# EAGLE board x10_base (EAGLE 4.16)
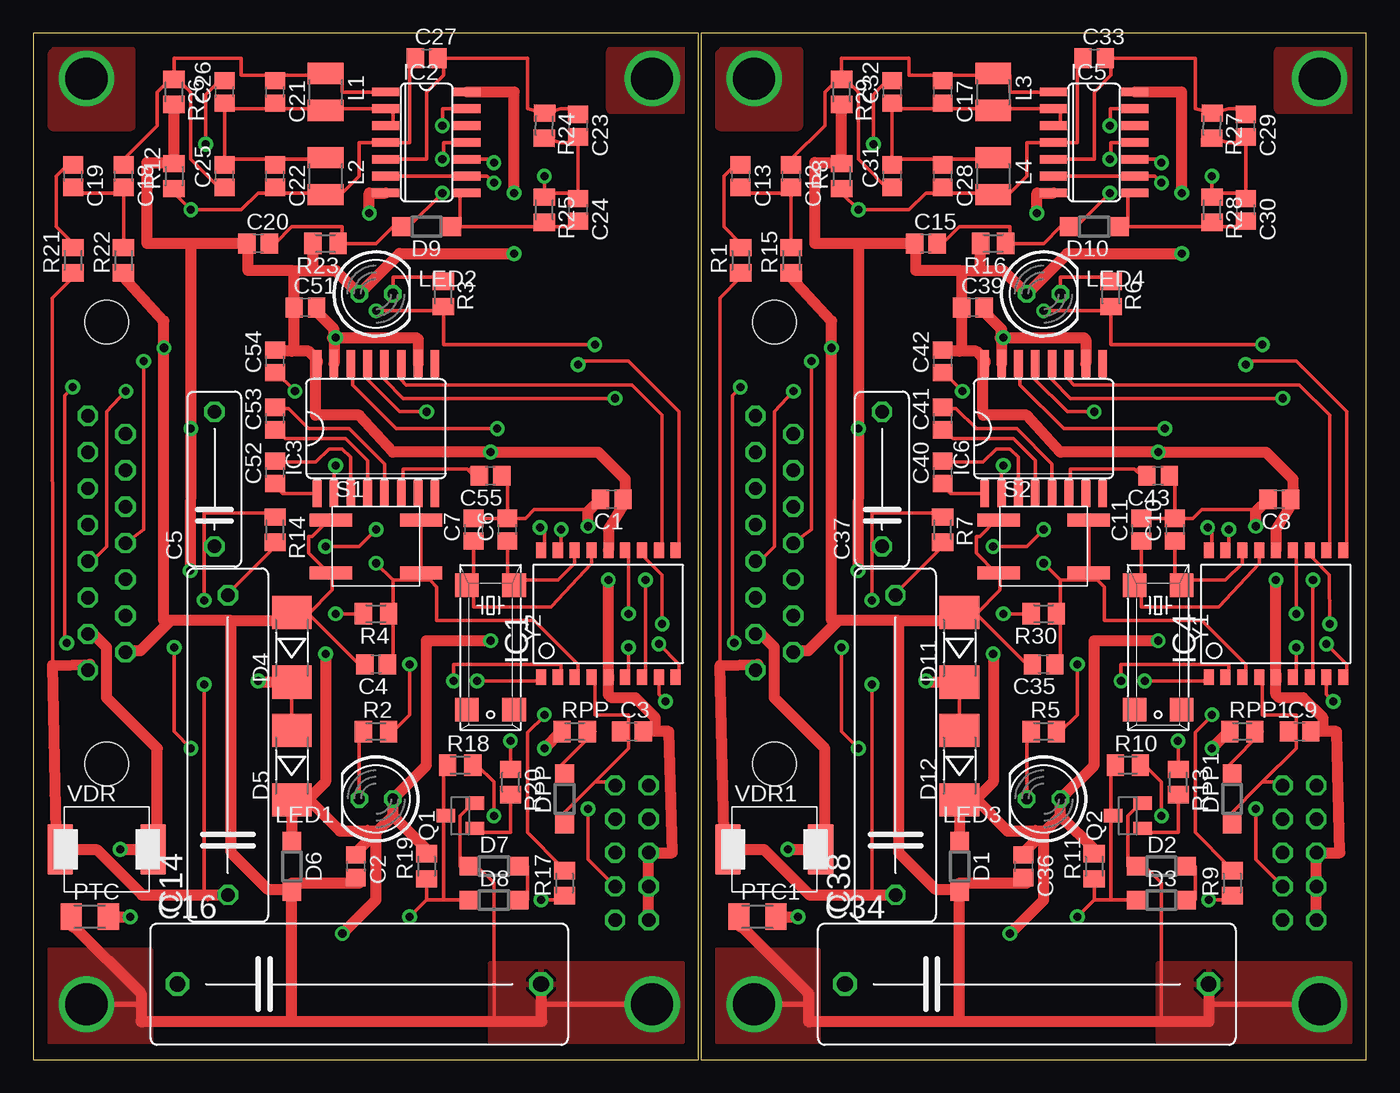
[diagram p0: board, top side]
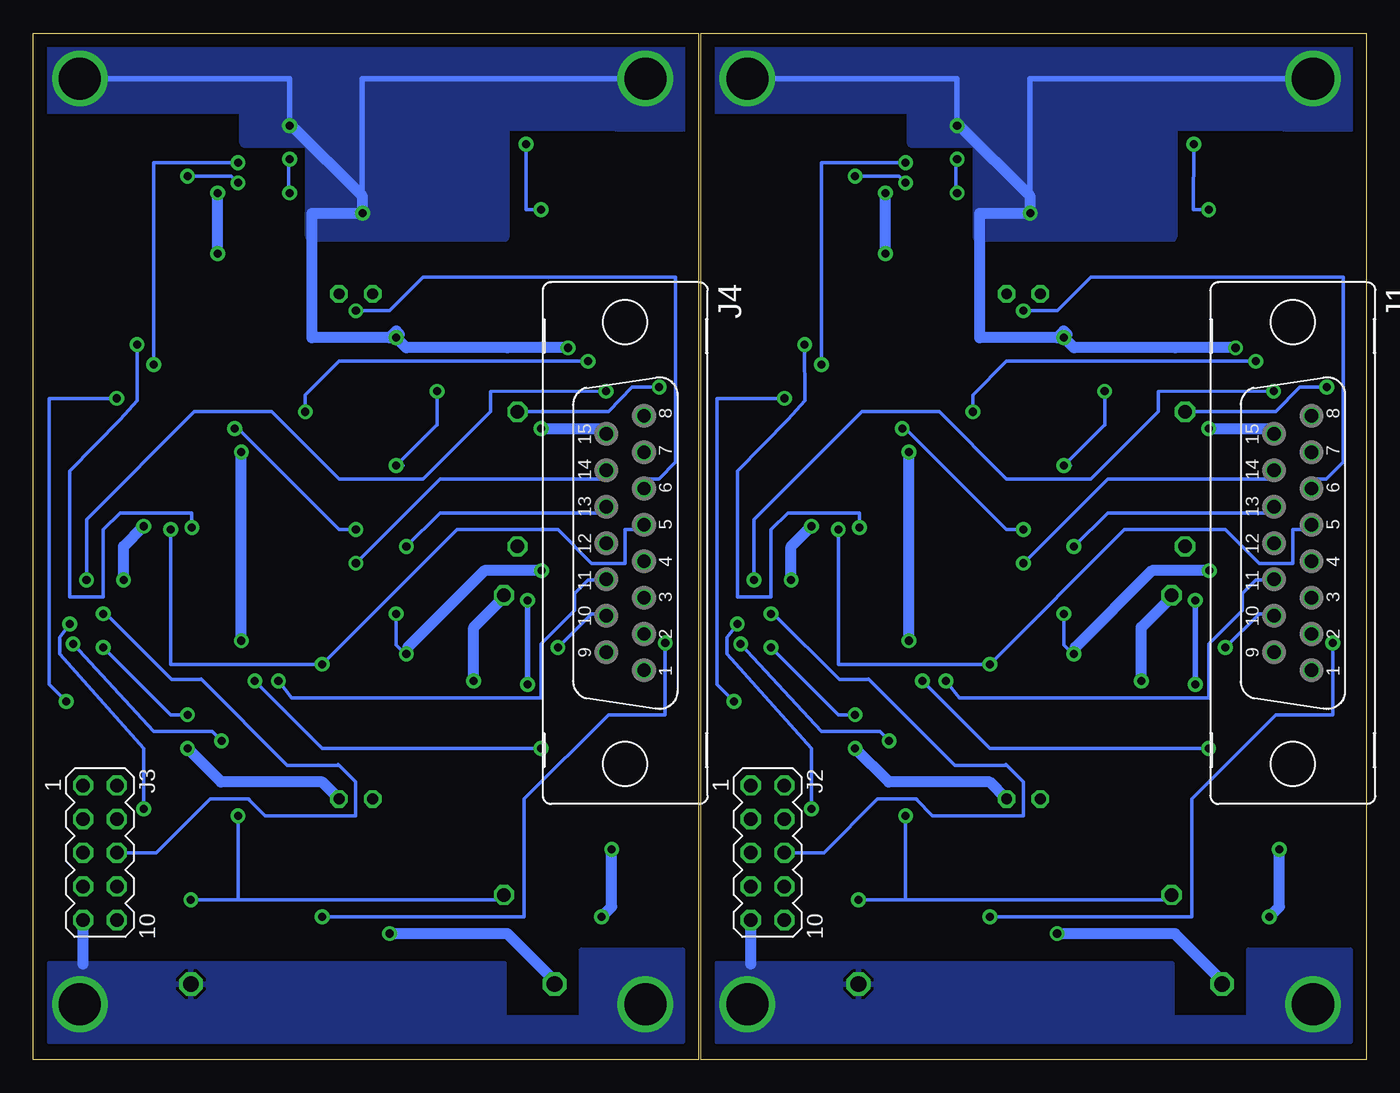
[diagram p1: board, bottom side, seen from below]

Size 100.58 x 77.46 mm. Coordinates in mm from the lower left corner, seen from the top.
Outline: 0,0 50.22,0 50.22,77.46 0,77.46 0,0
Outline: 50.37,0 100.58,0 100.58,77.46 50.37,77.46 50.37,0
Copper layers (1*16): Top 0.035mm / dielectric 1.5mm / Bottom 0.035mm
Design rules "default": minimum track width 10mil, minimum drill 24mil, track to track 10mil, track to pad 10mil, pad to pad 10mil, via to via 10mil, smd to smd 10mil, copper to edge 40mil, drill to drill 8mil, minimum pad ring 10mil, minimum via ring 10mil, stop-mask expansion 4mil, vias tented up to drill 0mil, thermal gap 10mil

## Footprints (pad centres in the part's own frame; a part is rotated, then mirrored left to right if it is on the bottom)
C0805 = smd 1.3 x 1.5: 1 -0.85,0; 2 0.85,0
C102-043X133 = drill 1.016 octagon: 1 -5.08,0; 2 5.08,0
C225-062X268 = drill 1.016 octagon: 1 -11.303,0; 2 11.303,0
C275-093X316 = drill 1.194 octagon: 1 -13.716,0; 2 13.716,0
SOD123 = smd 1.4 x 1.4: A 1.9,0; C -1.9,0
MELF-MLL41 = smd 2.5 x 3: A 2.625,0; C -2.625,0
SO-18W = smd 0.762 x 1.143: 1 -5.08,-4.788; 2 -3.81,-4.788; 3 -2.54,-4.788; 4 -1.27,-4.788; 5 0,-4.788; 6 1.27,-4.788; 7 2.54,-4.788; 8 3.81,-4.788; 9 5.08,-4.788; 10 5.08,4.788; 11 3.81,4.788; 12 2.54,4.788; 13 1.27,4.788; 14 0,4.788; 15 -1.27,4.788; 16 -2.54,4.788; 17 -3.81,4.788; 18 -5.08,4.788
SO14 = smd 0.66 x 2.032: 1 -3.81,-3.073; 2 -2.54,-3.073; 3 -1.27,-3.073; 4 0,-3.073; 5 1.27,-3.073; 6 2.54,-3.073; 7 3.81,-3.073; 8 3.81,3.073; 9 2.54,3.073; 10 1.27,3.073; 11 0,3.073; 12 -1.27,3.073; 13 -2.54,3.073; 14 -3.81,3.073
SO16L = smd 0.66 x 2.032: 1 -4.445,-4.902; 2 -3.175,-4.902; 3 -1.905,-4.902; 4 -0.635,-4.902; 5 0.635,-4.902; 6 1.905,-4.902; 7 3.175,-4.902; 8 4.445,-4.902; 9 4.445,4.902; 10 3.175,4.902; 11 1.905,4.902; 12 0.635,4.902; 13 -0.635,4.902; 14 -1.905,4.902; 15 -3.175,4.902; 16 -4.445,4.902
F15V = drill 1.016 octagon: 1 9.601,1.422; 2 6.858,1.422; 3 4.115,1.422; 4 1.372,1.422; 5 -1.372,1.422; 6 -4.115,1.422; 7 -6.858,1.422; 8 -9.601,1.422; 9 8.23,-1.422; 10 5.486,-1.422; 11 2.743,-1.422; 12 0,-1.422; 13 -2.743,-1.422; 14 -5.486,-1.422; 15 -8.23,-1.422 | hole 3.302: 16.662,0; -16.662,0
MA05-2 = drill 1.016 octagon: 1 -5.08,-1.27; 2 -5.08,1.27; 3 -2.54,-1.27; 4 -2.54,1.27; 5 0,-1.27; 6 0,1.27; 7 2.54,-1.27; 8 2.54,1.27; 9 5.08,-1.27; 10 5.08,1.27
L1210 = smd 1.6 x 2.7: 1 -1.4,0; 2 1.4,0
LED5MM = drill 0.813 octagon: A -1.27,0; K 1.27,0
M1206 = smd 1.6 x 2: 1 -1.4,0; 2 1.4,0
SOT23 = smd 1 x 1.4: 1 -0.95,-1.1; 2 0.95,-1.1; 3 0,1.1
M0805 = smd 1.3 x 1.6: 1 -0.95,0; 2 0.95,0
EVQQ2 = smd 3.2 x 1: A -3.4,-2; AP -3.4,2; B 3.4,-2; BP 3.4,2
VDR130V = smd 1.93 x 3.81: P$1 -3.5,0; P$2 3.5,0
MM39SL = smd 1.778 x 1.778: 1 -4.699,-1.778; 2 4.699,-1.778; 3 4.699,1.778; 4 -4.699,1.778

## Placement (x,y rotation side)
C1  0.1uF  [C0805]  43.65,42.29 180 top
C2  0.1uF  [C0805]  24.35,14.6 270 top
C3  0.1uF  [C0805]  45.17,24.76 0 top
C4  0.1uF  [C0805]  25.87,29.84 180 top
C5  0.1uF  [C102-043X133]  13.68,43.81 90 top
C6  15pF  [C0805]  35.78,40 90 top
C7  15pF  [C0805]  33.24,40 90 top
C8  0.1uF  [C0805]  94.02,42.29 180 top
C9  0.1uF  [C0805]  95.54,24.76 0 top
C10  15pF  [C0805]  86.14,40 90 top
C11  15pF  [C0805]  83.6,40 90 top
C12  150pF  [C0805]  57.19,66.67 270 top
C13  150pF  [C0805]  53.38,66.67 270 top
C14  1.0uF  [C225-062X268]  14.69,23.74 90 top
C15  0.01uF  [C0805]  67.35,61.59 0 top
C16  470uF  [C275-093X316]  24.6,5.71 0 top
C17  3300pF  [C0805]  68.62,73.02 270 top
C18  150pF  [C0805]  6.82,66.67 270 top
C19  150pF  [C0805]  3.01,66.67 270 top
C20  0.01uF  [C0805]  16.98,61.59 0 top
C21  3300pF  [C0805]  18.25,73.02 270 top
C22  3300pF  [C0805]  18.25,66.67 270 top
C23  10pF  [C0805]  41.11,70.48 270 top
C24  10pF  [C0805]  41.11,64.13 270 top
C25  4700pF  [C0805]  14.44,66.67 90 top
C26  4700pF  [C0805]  14.44,73.02 90 top
C27  100pF  [C0805]  29.68,75.56 0 top
C28  3300pF  [C0805]  68.62,66.67 270 top
C29  10pF  [C0805]  91.48,70.48 270 top
C30  10pF  [C0805]  91.48,64.13 270 top
C31  4700pF  [C0805]  64.81,66.67 90 top
C32  4700pF  [C0805]  64.81,73.02 90 top
C33  100pF  [C0805]  80.05,75.56 0 top
C34  470uF  [C275-093X316]  74.97,5.71 0 top
C35  0.1uF  [C0805]  76.24,29.84 180 top
C36  0.1uF  [C0805]  74.71,14.6 270 top
C37  0.1uF  [C102-043X133]  64.05,43.81 90 top
C38  1.0uF  [C225-062X268]  65.06,23.74 90 top
C39  0.1uF  [C0805]  70.9,56.76 0 top
C40  0.1uF  [C0805]  68.62,44.32 90 top
C41  0.1uF  [C0805]  68.62,48.38 90 top
C42  0.1uF  [C0805]  68.62,52.7 90 top
C43  0.1uF  [C0805]  84.87,44.06 180 top
C51  0.1uF  [C0805]  20.54,56.76 0 top
C52  0.1uF  [C0805]  18.25,44.32 90 top
C53  0.1uF  [C0805]  18.25,48.38 90 top
C54  0.1uF  [C0805]  18.25,52.7 90 top
C55  0.1uF  [C0805]  34.51,44.06 180 top
D1  5.1V  [SOD123]  69.89,14.6 270 top
D2  6.8V  [SOD123]  85.13,14.6 0 top
D3  6.8V  [SOD123]  85.13,12.06 0 top
D4  DL4005  [MELF-MLL41]  19.52,31.11 90 top
D5  DL4005  [MELF-MLL41]  19.52,22.22 90 top
D6  5.1V  [SOD123]  19.52,14.6 270 top
D7  6.8V  [SOD123]  34.76,14.6 0 top
D8  6.8V  [SOD123]  34.76,12.06 0 top
D9  1N4148S  [SOD123]  29.68,62.86 180 top
D10  1N4148S  [SOD123]  80.05,62.86 180 top
D11  DL4005  [MELF-MLL41]  69.89,31.11 90 top
D12  DL4005  [MELF-MLL41]  69.89,22.22 90 top
DPP  1N4148S  [SOD123]  40.09,19.68 90 top
DPP1  1N4148S  [SOD123]  90.46,19.68 90 top
IC1  PIC16F87ASO  [SO-18W]  43.4,33.65 0 top
IC2  4069D  [SO14]  29.68,69.21 270 top
IC3  MAX232ECWE  [SO16L]  25.87,47.62 0 top
IC4  PIC16F87ASO  [SO-18W]  93.76,33.65 0 top
IC5  4069D  [SO14]  80.05,69.21 270 top
IC6  MAX232ECWE  [SO16L]  76.24,47.62 0 top
J1  [F15V]  5.55,38.98 270 bottom
J2  [MA05-2]  45.17,15.62 270 bottom
J3  [MA05-2]  95.54,15.62 270 bottom
J4  [F15V]  55.92,38.98 270 bottom
L1  220uH  [L1210]  22.06,73.02 270 top
L2  220uH  [L1210]  22.06,66.67 270 top
L3  220uH  [L1210]  72.43,73.02 270 top
L4  220uH  [L1210]  72.43,66.67 270 top
LED1  [LED5MM]  25.87,19.68 180 top
LED2  [LED5MM]  25.87,57.78 0 top
LED3  [LED5MM]  76.24,19.68 180 top
LED4  [LED5MM]  76.24,57.78 0 top
PTC  [M1206]  4.28,10.79 0 top
PTC1  [M1206]  54.65,10.79 0 top
Q1  2N2222S  [SOT23]  32.22,18.41 90 top
Q2  2N2222S  [SOT23]  82.59,18.41 90 top
R1  10K  [M0805]  53.38,60.32 90 top
R2  680  [M0805]  25.87,24.76 0 top
R3  680  [M0805]  30.95,57.78 270 top
R4  10K  [M0805]  25.87,33.65 180 top
R5  680  [M0805]  76.24,24.76 0 top
R6  680  [M0805]  81.32,57.78 270 top
R7  1M  [M0805]  68.62,40 270 top
R8  470K  [M0805]  61,66.67 90 top
R9  5M  [M0805]  90.46,13.33 90 top
R10  1M  [M0805]  82.59,22.22 0 top
R11  50  [M0805]  80.05,14.6 90 top
R12  470K  [M0805]  10.63,66.67 90 top
R13  200  [M0805]  86.4,20.95 270 top
R14  1M  [M0805]  18.25,40 270 top
R15  33K  [M0805]  57.19,60.32 90 top
R16  100K  [M0805]  72.43,61.59 180 top
R17  5M  [M0805]  40.09,13.33 90 top
R18  1M  [M0805]  32.22,22.22 0 top
R19  50  [M0805]  29.68,14.6 90 top
R20  200  [M0805]  36.03,20.95 270 top
R21  10K  [M0805]  3.01,60.32 90 top
R22  33K  [M0805]  6.82,60.32 90 top
R23  100K  [M0805]  22.06,61.59 180 top
R24  220K  [M0805]  38.57,70.48 268.8 top
R25  27K  [M0805]  38.57,64.13 270 top
R26  10M  [M0805]  10.63,73.02 270 top
R27  220K  [M0805]  88.94,70.48 268.8 top
R28  27K  [M0805]  88.94,64.13 270 top
R29  10M  [M0805]  61,73.02 270 top
R30  10K  [M0805]  76.24,33.65 180 top
RPP  10K  [M0805]  40.86,24.76 0 top
RPP1  10K  [M0805]  91.22,24.76 0 top
S1  EVQQ2  [EVQQ2]  25.87,38.73 0 top
S2  EVQQ2  [EVQQ2]  76.24,38.73 0 top
VDR  VARISTORVDR130V  [VDR130V]  5.55,15.87 0 top
VDR1  VARISTORVDR130V  [VDR130V]  55.92,15.87 0 top
Y1  7.68MHz  [MM39SL]  84.87,31.11 270 top
Y2  7.68MHz  [MM39SL]  34.51,31.11 270 top

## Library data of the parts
C1-C43 C51-C55 L1-L4 PTC PTC1 R1-R30 RPP RPP1 = rcl
D1-D12 DPP DPP1 = diode
IC1 IC4 = microchip
IC2 IC5 = 40xx
IC3 IC6 = maxim
J1 J4 = con-subd
J2 J3 = con-lstb
LED1-LED4 = led
Q1 Q2 = transistor-npn
S1 S2 = switch
VDR VDR1 = varistor
Y1 Y2 = crystal

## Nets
+5V: C1.1 C2.1 C16.1 C20.1 C51.1 C54.2 D5.C D6.C IC1.14 IC2.14 IC3.16 J1.15 LED1.A LED2.A R4.2 R12.2 R19.2 R23.2 R26.2 RPP.1
+5V1: C8.1 C15.1 C34.1 C36.1 C39.1 C42.2 D1.C D12.C IC4.14 IC5.14 IC6.16 J4.15 LED3.A LED4.A R8.2 R11.2 R16.2 R29.2 R30.2 RPP1.1
CTL1: IC1.1 J1.10
CTL2: IC1.2 J1.11
CTL3: IC4.2 J4.11
CTL4: IC4.1 J4.10
GND: C1.2 C2.2 C3.2 C4.2 C6.2 C7.2 C16.2 C51.2 C55.1 D4.A D6.A D7.C IC1.5 IC2.7 IC2.13 IC3.10 IC3.15 J1.9 J2.5 J2.7 J2.9 PTC.1 Q1.2 R22.1 S1.A S1.AP
GND1: C8.2 C9.2 C10.2 C11.2 C34.2 C35.2 C36.2 C39.2 C43.1 D1.A D2.C D11.A IC4.5 IC5.7 IC5.13 IC6.10 IC6.15 J3.5 J3.7 J3.9 J4.9 PTC1.1 Q2.2 R15.1 S2.A S2.AP
HOT: C5.1 C14.1 J1.1 R14.1 R17.1 R18.2 R21.1 VDR.P$1
HOT1: C37.1 C38.1 J4.1 R1.1 R7.1 R9.1 R10.2 VDR1.P$1
LED1: IC1.17 J1.5 R2.2
LED2: IC1.18 J1.6 R3.2
LED3: IC4.17 J4.5 R5.2
LED4: IC4.18 J4.6 R6.2
N$1: DPP.A RPP.2
N$2: Q1.1 R20.2
N$3: C6.1 IC1.16 Y2.4
N$4: C7.1 IC1.15 Y2.1
N$5: LED1.K R2.1
N$6: LED2.K R3.1
N$7: IC3.14 J1.13
N$8: C52.1 IC3.1
N$9: C14.2 D4.C D5.A R14.2
N$10: C52.2 IC3.3
N$11: C5.2 D8.C Q1.3 R18.1 R19.1
N$12: D7.A D8.A
N$13: C23.1 C27.2 IC2.5 R24.1
N$14: C23.2 C24.1 IC2.6 IC2.9 R24.2 R25.1
N$15: C18.1 C21.1 C25.1 IC2.1 L1.1 R26.1
N$16: C19.1 R21.2
N$17: C18.2 C19.2 R22.2
N$18: C21.2 C22.1 C25.2 C26.1 IC2.2 IC2.3 L1.2 L2.1
N$19: C22.2 C26.2 C27.1 IC2.4 L2.2 R12.1
N$20: C24.2 D9.C IC2.8 R25.2
N$21: C20.2 D9.A IC2.11 R23.1
N$22: C53.1 IC3.4
N$23: C53.2 IC3.5
N$24: C54.1 IC3.2
N$25: C55.2 IC3.6
N$26: IC3.13 J1.12
N$27: C11.1 IC4.15 Y1.1
N$28: C10.1 IC4.16 Y1.4
N$29: LED3.K R5.1
N$30: LED4.K R6.1
N$31: C38.2 D11.C D12.A R7.2
N$32: C37.2 D3.C Q2.3 R10.1 R11.1
N$33: D2.A D3.A
N$34: C29.1 C33.2 IC5.5 R27.1
N$35: C29.2 C30.1 IC5.6 IC5.9 R27.2 R28.1
N$36: C13.1 R1.2
N$37: C12.2 C13.2 R15.2
N$38: C12.1 C17.1 C31.1 IC5.1 L3.1 R29.1
N$39: C17.2 C28.1 C31.2 C32.1 IC5.2 IC5.3 L3.2 L4.1
N$40: C28.2 C32.2 C33.1 IC5.4 L4.2 R8.1
N$41: C30.2 D10.C IC5.8 R28.2
N$42: C15.2 D10.A IC5.11 R16.1
N$43: DPP1.A RPP1.2
N$44: Q2.1 R13.2
N$45: C40.1 IC6.1
N$46: C40.2 IC6.3
N$47: C41.1 IC6.4
N$48: C41.2 IC6.5
N$49: IC6.14 J4.13
N$50: IC6.13 J4.12
N$51: C42.1 IC6.2
N$52: C43.2 IC6.6
NEUT: J1.2 PTC.2 VDR.P$2
NEUT1: J4.2 PTC1.2 VDR1.P$2
RB1: IC4.12 J3.8
RB2: IC4.13 J3.6
RB6: IC1.12 J2.8
RB7: IC1.13 J2.6
SIN: IC1.8 IC3.12
SIN1: IC4.8 IC6.12
SOUT: IC1.11 IC3.11
SOUT1: IC4.11 IC6.11
SWIN: C4.1 IC1.3 J1.14 R4.1 S1.B S1.BP
SWIN1: C35.1 IC4.3 J4.14 R30.1 S2.B S2.BP
UTIL: IC1.7 J1.4
UTIL1: IC4.7 J4.4
VPP: C3.1 DPP.C IC1.4 J2.2
VPP1: C9.1 DPP1.C IC4.4 J3.2
XIN: IC1.10 IC2.10
XIN1: IC4.10 IC5.10
XOUT: IC1.9 R20.1
XOUT1: IC4.9 R13.1
ZEROX: IC1.6 R17.2
ZEROX1: IC4.6 R9.2

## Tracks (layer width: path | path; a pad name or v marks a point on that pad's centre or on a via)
+5V  (via drill 0.61)
  Top 0.254: 10.63,67.43 R12.2 10.63,67.69 | C20.1 15.71,61.59 | 44.67,42.54 C1.1 | 21.3,52.7 21.17,53.08 | 24.6,15.87 C2.1 | 29.68,15.87 R19.2 | 39.84,24.76 RPP.1 | 20.79,19.68 D5.C | v22.82,33.65 R4.2
  Top 0.813: IC1.14 43.4,40 44.67,42.03 C1.1 | 19.52,16.38 D6.C D5.C 20.82,19.59 23.15,17.27 25.29,17.27 | IC3.16 21.42,52.83 21.17,53.08 20.79,53.46 19.52,53.46 | C54.2 18.25,53.46 19.52,53.46 | 19.52,53.46 19.69,53.63 C51.1 19.69,59.39 19.52,59.56 | 19.52,59.56 16.22,59.56 16.22,61.59 C20.1 | R23.2 21.11,59.62 21.04,59.56 | 19.52,59.56 21.04,59.56 | 15.71,61.59 11.9,61.59 | 11.9,61.59 8.6,61.59 8.6,67.69 10.63,67.69 | R12.2 R26.2 | v36.28,65.4 36.28,73.02 IC2.14 | 44.67,42.54 44.67,43.81 42.63,45.84 v34.51,45.84 27.14,45.84 24.6,48.64 21.3,48.64 21.3,52.7 | 25.87,17.14 27.14,18.41 | 25.87,17.14 24.6,15.87 | 27.14,18.41 LED1.A 29.68,22.22 29.68,31.62 v34.51,31.62 | 27.14,18.41 29.68,15.87 | v38.57,23.49 39.84,24.76 | v23.33,9.52 25.87,12.06 25.87,17.14 | 11.9,61.59 v11.9,47.62 v11.85,36.9 | 20.79,19.68 22.06,20.95 v22.06,30.63 | 21.04,59.56 22.82,59.56 LED2.A 27.65,60.83 v36.28,60.83 | 25.29,17.27 25.97,17.27 | 25.29,17.27 25.26,17.29 25.21,17.29
  Bottom 0.254: C16.1 10.63,5.71 | v22.06,30.63 22.06,30.55 22.82,31.31 v22.82,33.65
  Bottom 0.813: v38.57,23.49 36.03,20.95 28.41,20.95 LED1.A | 10.63,5.71 14.44,9.52 v23.33,9.52 | v11.9,47.62 6.82,47.62 J1.15 | v34.51,31.62 v34.51,45.84 | v36.28,60.83 v36.28,65.4 | v11.85,36.9 16.17,36.9 21.96,31.11 v22.06,30.63
+5V1  (via drill 0.61)
  Top 0.254: 61,67.43 R8.2 61,67.69 | C15.1 66.08,61.59 | 95.03,42.54 C8.1 | 71.67,52.7 71.54,53.08 | 74.97,15.87 C36.1 | 80.05,15.87 R11.2 | 90.21,24.76 RPP1.1 | 71.16,19.68 D12.C | v73.19,33.65 R30.2
  Top 0.813: IC4.14 93.76,40 95.03,42.03 C8.1 | 69.89,16.38 D1.C D12.C 71.19,19.59 73.52,17.27 75.65,17.27 | IC6.16 71.79,52.83 71.54,53.08 71.16,53.46 69.89,53.46 | C42.2 68.62,53.46 69.89,53.46 | 69.89,53.46 70.05,53.63 C39.1 70.05,59.39 69.89,59.56 | 69.89,59.56 66.59,59.56 66.59,61.59 C15.1 | R16.2 71.48,59.62 71.41,59.56 | 69.89,59.56 71.41,59.56 | 66.08,61.59 62.27,61.59 | 62.27,61.59 58.97,61.59 58.97,67.69 61,67.69 | R8.2 R29.2 | v86.65,65.4 86.65,73.02 IC5.14 | 95.03,42.54 95.03,43.81 93,45.84 v84.87,45.84 77.51,45.84 74.97,48.64 71.67,48.64 71.67,52.7 | 76.24,17.14 77.51,18.41 | 76.24,17.14 74.97,15.87 | 77.51,18.41 LED3.A 80.05,22.22 80.05,31.62 v84.87,31.62 | 77.51,18.41 80.05,15.87 | v88.94,23.49 90.21,24.76 | v73.7,9.52 76.24,12.06 76.24,17.14 | 62.27,61.59 v62.27,47.62 v62.22,36.9 | 71.16,19.68 72.43,20.95 v72.43,30.63 | 71.41,59.56 73.19,59.56 LED4.A 78.02,60.83 v86.65,60.83 | 75.65,17.27 76.34,17.27 | 75.65,17.27 75.63,17.29 75.58,17.29
  Bottom 0.254: C34.1 61,5.71 | v72.43,30.63 72.43,30.55 73.19,31.31 v73.19,33.65
  Bottom 0.813: v88.94,23.49 86.4,20.95 78.78,20.95 LED3.A | 61,5.71 64.81,9.52 v73.7,9.52 | v62.27,47.62 57.19,47.62 J4.15 | v84.87,31.62 v84.87,45.84 | v86.65,60.83 v86.65,65.4 | v62.22,36.9 66.53,36.9 72.33,31.11 v72.43,30.63
CTL1  (via drill 0.61)
  Top 0.254: v33.49,28.57 38.57,28.57 IC1.1 | v11.9,23.49 10.63,24.76 v10.63,31.11
  Bottom 0.254: v33.49,28.57 28.41,23.49 v11.9,23.49 | v10.63,31.11 8.09,33.65 6.82,33.65 J1.10
CTL2  (via drill 0.61)
  Top 0.254: 39.59,28.57 IC1.2 39.84,28.57 39.84,29.84 31.71,29.84 v31.71,28.57
  Bottom 0.254: v31.71,28.57 30.7,27.3 11.9,27.3 11.9,31.36 9.36,33.9 9.36,35.17 8.34,36.19 6.82,36.19 J1.11
CTL3  (via drill 0.61)
  Top 0.254: 89.95,28.57 IC4.2 90.21,28.57 90.21,29.84 82.08,29.84 v82.08,28.57
  Bottom 0.254: v82.08,28.57 81.06,27.3 62.27,27.3 62.27,31.36 59.73,33.9 59.73,35.17 58.71,36.19 57.19,36.19 J4.11
CTL4  (via drill 0.61)
  Top 0.254: v83.86,28.57 88.94,28.57 IC4.1 | v62.27,23.49 61,24.76 v61,31.11
  Bottom 0.254: v83.86,28.57 78.78,23.49 v62.27,23.49 | v61,31.11 58.46,33.65 57.19,33.65 J4.10
GND  (via drill 0.61, 3.17)
  Top 0.254: 38.37,5.68 C16.2 | 24.6,13.33 C2.2 | D6.A 19.52,13.33 | 20.79,33.65 24.6,29.84 C4.2 | D4.A 20.79,33.65 | 6.82,59.05 R22.1 | 20.79,33.65 22.57,35.43 22.57,36.7 22.5,36.7 S1.A 22.28,36.73 20.79,38.22 20.79,39.49 21.04,39.49 22.31,40.76 22.35,40.73 S1.AP | 33.24,41.27 C7.2 35.69,40.85 35.78,40.76 C6.2 | C6.2 37.13,40.85 37.81,41.52 41.87,41.52 41.95,41.44 | C55.1 35.36,43.98 35.78,43.56 C6.2 | 34.76,2.92 34.76,13.33 33.49,14.6 D7.C 32.22,14.6 32.22,18.41 33.49,19.68 Q1.2 | v30.87,70.48 30.9,70.48 30.9,71.75 32.85,71.75 | 32.85,71.75 IC2.13 | 32.85,71.75 32.85,71.77
  Top 0.406: 8.01,5 8.01,5.08 | 8.01,5 8.14,5 | v4.03,4.19 8.01,4.19 8.01,5 | v46.7,4.19 38.29,4.19 38.29,5.71
  Top 0.813: J2.9 J2.7 J2.5 48.22,15.62 47.97,24.76 C3.2 46.95,24.93 46.95,25.78 45.43,27.3 43.65,27.3 43.4,27.55 43.4,29.08 | 8.19,2.92 8.14,2.92 | 8.19,2.92 19.52,2.92 | 19.52,2.92 34.76,2.92 38.37,2.89 38.37,5.68 | PTC.1 3.01,10.79 3.01,10.03 3.11,10.03 8.14,5 8.14,2.89 8.19,2.84 8.19,2.92 | C1.2 41.95,41.44 41.87,41.36 v41.87,40.25 | 43.4,28.57 IC1.5 43.4,29.08 | 43.4,29.08 v43.4,36.19 | 19.52,2.92 D6.A 19.4,12.82 17.74,12.82 14.95,15.62 14.95,33.14 | D4.A 18.93,33.14 14.95,33.14 | 14.95,33.14 9.87,33.14 | 9.87,33.14 10.38,33.14 8.09,30.86 7.07,30.86 J1.9 | 19.52,13.33 24.6,13.33 | 6.82,59.05 9.87,55.75 v9.87,53.72 9.87,33.14 | C51.2 21.39,56.6 21.3,56.51 22.7,55.11 22.7,54.48 | 22.7,54.48 IC3.15 | IC3.10 29.04,54.35 28.92,54.48 v22.82,54.48 22.7,54.48 | 22.7,54.48 22.57,54.48 | IC2.7 25.36,65.4 v25.36,63.88
  Bottom 0.254: 14.44,53.72 14.44,53.97 | 30.7,70.48 v30.87,70.48
  Bottom 0.406: v46.7,74.04 30.87,74.04 30.87,70.4 | v4.03,74.04 25.39,74.04 25.39,63.77
  Bottom 0.813: v41.87,40.25 43.4,38.73 v43.4,36.19 | v9.87,53.72 14.44,53.72 22.06,53.72 v22.82,54.48 22.57,54.73 22.82,54.99 23.33,54.48 29.17,54.48 29.17,63.88 v25.36,63.88 25.36,65.15 30.7,70.48 | 46.44,7.23 J2.9
  pour Top: 43.65,71.75 43.65,76.07 48.98,76.07 48.98,71.75
  pour Top: 1.49,70.48 7.33,70.48 7.33,76.07 1.74,76.07 1.49,75.81
  pour Top: 1.23,1.39 1.23,8.25 8.85,8.25 8.85,1.39
  pour Top: 48.98,1.39 48.98,7.23 34.51,7.23 34.51,1.39
  pour Bottom: 1.23,1.39 1.23,8.25 8.85,8.25 8.85,3.17 14.69,3.17 14.69,7.23 48.98,7.23 48.98,1.39
  pour Bottom: 0.98,76.32 0.98,70.48 6.31,70.48 0.98,70.48 14.69,70.48 14.69,62.1 29.27,62.1 29.27,69.21 34.25,69.21 34.25,71.75 48.98,71.75 48.98,76.32
GND1  (via drill 0.61, 3.17)
  Top 0.254: 88.73,5.68 C34.2 | 74.97,13.33 C36.2 | D1.A 69.89,13.33 | 71.16,33.65 74.97,29.84 C35.2 | D11.A 71.16,33.65 | 57.19,59.05 R15.1 | 71.16,33.65 72.94,35.43 72.94,36.7 72.87,36.7 S2.A 72.65,36.73 71.16,38.22 71.16,39.49 71.41,39.49 72.68,40.76 72.71,40.73 S2.AP | 83.6,41.27 C11.2 86.06,40.85 86.14,40.76 C10.2 | C10.2 87.5,40.85 88.18,41.52 92.24,41.52 92.32,41.44 | C43.1 85.72,43.98 86.14,43.56 C10.2 | 85.13,2.92 85.13,13.33 83.86,14.6 D2.C 82.59,14.6 82.59,18.41 83.86,19.68 Q2.2 | v81.24,70.48 81.27,70.48 81.27,71.75 83.22,71.75 | 83.22,71.75 IC5.13 | 83.22,71.75 83.22,71.77
  Top 0.406: 58.38,5 58.38,5.08 | 58.38,5 58.51,5 | v54.39,4.19 58.38,4.19 58.38,5 | v97.07,4.19 88.66,4.19 88.66,5.71
  Top 0.813: J3.9 J3.7 J3.5 98.59,15.62 98.34,24.76 C9.2 97.32,24.93 97.32,25.78 95.8,27.3 94.02,27.3 93.76,27.55 93.76,29.08 | 58.56,2.92 58.51,2.92 | 58.56,2.92 69.89,2.92 | 69.89,2.92 85.13,2.92 88.73,2.89 88.73,5.68 | PTC1.1 53.38,10.79 53.38,10.03 53.48,10.03 58.51,5 58.51,2.89 58.56,2.84 58.56,2.92 | C8.2 92.32,41.44 92.24,41.36 v92.24,40.25 | 93.76,28.57 IC4.5 93.76,29.08 | 93.76,29.08 v93.76,36.19 | 69.89,2.92 D1.A 69.77,12.82 68.11,12.82 65.32,15.62 65.32,33.14 | D11.A 69.3,33.14 65.32,33.14 | 65.32,33.14 60.24,33.14 | 60.24,33.14 60.74,33.14 58.46,30.86 57.44,30.86 J4.9 | 69.89,13.33 74.97,13.33 | 57.19,59.05 60.24,55.75 v60.24,53.72 60.24,33.14 | C39.2 71.75,56.6 71.67,56.51 73.06,55.11 73.06,54.48 | 73.06,54.48 IC6.15 | IC6.10 79.41,54.35 79.29,54.48 v73.19,54.48 73.06,54.48 | 73.06,54.48 72.94,54.48 | IC5.7 75.73,65.4 v75.73,63.88
  Bottom 0.254: 64.81,53.72 64.81,53.97 | 81.06,70.48 v81.24,70.48
  Bottom 0.406: v97.07,74.04 81.24,74.04 81.24,70.4 | v54.39,74.04 75.76,74.04 75.76,63.77
  Bottom 0.813: v92.24,40.25 93.76,38.73 v93.76,36.19 | v60.24,53.72 64.81,53.72 72.43,53.72 v73.19,54.48 72.94,54.73 73.19,54.99 73.7,54.48 79.54,54.48 79.54,63.88 v75.73,63.88 75.73,65.15 81.06,70.48 | 96.81,7.23 J3.9
  pour Top: 94.02,71.75 94.02,76.07 99.35,76.07 99.35,71.75
  pour Top: 51.85,70.48 57.7,70.48 57.7,76.07 52.11,76.07 51.85,75.81
  pour Top: 51.6,1.39 51.6,8.25 59.22,8.25 59.22,1.39
  pour Top: 99.35,1.39 99.35,7.23 84.87,7.23 84.87,1.39
  pour Bottom: 51.6,1.39 51.6,8.25 59.22,8.25 59.22,3.17 65.06,3.17 65.06,7.23 99.35,7.23 99.35,1.39
  pour Bottom: 51.35,76.32 51.35,70.48 56.68,70.48 51.35,70.48 65.06,70.48 65.06,62.1 79.64,62.1 79.64,69.21 84.62,69.21 84.62,71.75 99.35,71.75 99.35,76.32
HOT  (via drill 0.61)
  Top 0.254: 1.46,29.76 1.44,57.45 3.01,59.05 R21.1 | VDR.P$1 1.74,17.14 | 4.28,29.84 J1.1 | 12.92,38.73 12.92,41.27 18.25,41.27 R14.1 | v12.92,28.32 12.92,12.44 13.17,12.06 | v12.92,34.67 12.92,38.73 | 12.92,38.73 C5.1 | v38.32,12.06 39.84,12.06 R17.1 | v34.76,18.41 34.76,20.95 33.49,22.22 R18.2
  Top 0.813: 1.74,17.14 1.46,29.76 4.28,29.84 | C14.1 12.92,12.44 8.22,12.44 4.79,15.87 VDR.P$1
  Bottom 0.254: 34.76,12.06 14.44,12.06 C14.1 | 34.76,12.06 v38.32,12.06 | 34.76,12.06 v34.76,18.41
  Bottom 0.406: v12.92,28.32 v12.92,34.67
HOT1  (via drill 0.61)
  Top 0.254: 51.83,29.76 51.8,57.45 53.38,59.05 R1.1 | VDR1.P$1 52.11,17.14 | 54.65,29.84 J4.1 | 63.28,38.73 63.28,41.27 68.62,41.27 R7.1 | v63.28,28.32 63.28,12.44 63.54,12.06 | v63.28,34.67 63.28,38.73 | 63.28,38.73 C37.1 | v88.68,12.06 90.21,12.06 R9.1 | v85.13,18.41 85.13,20.95 83.86,22.22 R10.2
  Top 0.813: 52.11,17.14 51.83,29.76 54.65,29.84 | C38.1 63.28,12.44 58.59,12.44 55.16,15.87 VDR1.P$1
  Bottom 0.254: 85.13,12.06 64.81,12.06 C38.1 | 85.13,12.06 v88.68,12.06 | 85.13,12.06 v85.13,18.41
  Bottom 0.406: v63.28,28.32 v63.28,34.67
LED1  (via drill 0.61)
  Top 0.254: v39.84,40 39.84,38.73 IC1.17 | v28.41,29.84 28.41,26.03 27.14,24.76 R2.2
  Bottom 0.254: v39.84,40 39.84,29.84 v28.41,29.84 18.25,40 10.63,40 8.09,37.46 5.55,37.46 5.55,40 4.28,40 J1.5
LED2  (via drill 0.61)
  Top 0.254: v42.38,53.97 30.95,53.97 30.95,56.51 | v25.87,56.51 30.95,56.51 | 30.95,56.51 R3.2 | v38.24,40.15 38.57,40 38.57,38.73 IC1.18
  Bottom 0.254: v42.38,53.97 42.35,49.75 43.65,48.31 47.46,44.42 47.46,34.92 44.92,34.92 44.92,40 43.65,41.27 38.24,41.27 v38.24,40.15 38.24,40 | v25.87,56.51 23.33,56.51 20.79,59.05 1.74,59.05 1.74,45.08 3.01,43.81 4.28,43.81 J1.6
LED3  (via drill 0.61)
  Top 0.254: v90.21,40 90.21,38.73 IC4.17 | v78.78,29.84 78.78,26.03 77.51,24.76 R5.2
  Bottom 0.254: v90.21,40 90.21,29.84 v78.78,29.84 68.62,40 61,40 58.46,37.46 55.92,37.46 55.92,40 54.65,40 J4.5
LED4  (via drill 0.61)
  Top 0.254: v92.75,53.97 81.32,53.97 81.32,56.51 | v76.24,56.51 81.32,56.51 | 81.32,56.51 R6.2 | v88.61,40.15 88.94,40 88.94,38.73 IC4.18
  Bottom 0.254: v92.75,53.97 92.72,49.75 94.02,48.31 97.83,44.42 97.83,34.92 95.29,34.92 95.29,40 94.02,41.27 88.61,41.27 v88.61,40.15 88.61,40 | v76.24,56.51 73.7,56.51 71.16,59.05 52.11,59.05 52.11,45.08 53.38,43.81 54.65,43.81 J4.6
N$1
  Top 0.254: DPP.A 39.84,22.22 42.38,24.76 RPP.2
N$2
  Top 0.254: Q1.1 33.49,17.14 36.03,17.14 R20.2
N$3
  Top 0.254: 40.86,38.73 IC1.16 40.86,37.46 39.59,36.19 37.05,36.19 Y2.4 35.78,36.19 C6.1
N$4
  Top 0.254: 33.24,36.19 33.24,34.16 39.08,34.16 42.13,37.46 IC1.15 42.13,38.73 | 33.24,36.19 C7.1 | Y2.1 33.24,36.19
N$5
  Top 0.254: LED1.K 24.6,24.76 R2.1
N$6
  Top 0.254: LED2.K 27.14,59.05 30.95,59.05 R3.1
N$7  (via drill 0.61)
  Top 0.254: v35.01,47.62 27.39,47.62 24.09,50.92 24.09,52.45 24.02,52.52 IC3.14 | v25.87,40 24.6,38.73 v22.06,38.73
  Bottom 0.254: v25.87,40 27.14,40 34.76,47.62 v35.01,47.62 | v22.06,38.73 19.52,41.27 6.82,41.27 J1.13
N$8
  Top 0.254: C52.1 18.25,43.3 18.83,42.72 IC3.1
N$9  (via drill 0.61)
  Top 0.254: D5.A D4.C | R14.2 18.25,38.73 14.44,34.92 C14.2
  Top 0.813: D4.C 17.06,28.48 v16.98,28.57
  Bottom 0.813: C14.2 14.69,34.92 16.98,32.63 v16.98,28.57
N$10
  Top 0.254: IC3.3 23.96,45.46 23.33,46.1 22.31,46.1 21.3,45.08 18.5,45.08 18.42,45.17 C52.2
N$11  (via drill 0.61)
  Top 0.254: C5.2 13.17,48.89 | 30.95,18.41 30.95,22.22 R18.1 | 29.68,12.06 30.95,12.06 | 30.95,12.06 D8.C | 29.68,12.06 R19.1 | 30.95,12.06 30.95,18.41 | 30.95,18.41 Q1.3 | v28.41,10.79 29.68,12.06 | v2.53,31.44 2.4,31.44 2.4,50.11 2.99,50.69 v2.99,50.74
  Bottom 0.254: v2.99,50.74 5.02,50.74 6.82,48.89 C5.2 | v28.41,10.79 13.17,10.79 13.17,19.68 6.82,26.03 2.53,26.03 v2.53,31.44
N$12
  Top 0.254: D8.A 37.3,12.06 37.3,14.6 D7.A
N$13
  Top 0.254: 30.95,75.56 37.3,75.56 37.3,71.75 R24.1 39.84,71.75 41.11,71.75 C23.1 | 30.95,75.56 30.95,74.29 29.68,73.02 29.68,67.94 IC2.5 | 30.95,75.56 C27.2
N$14  (via drill 0.61)
  Top 0.254: 38.57,65.4 41.11,65.4 | 41.11,69.21 39.84,69.21 R24.2 | 41.11,65.4 41.11,69.21 | 41.11,65.4 C24.1 | 41.11,69.21 C23.2 | IC2.6 IC2.9 34.25,66.67 v34.76,66.16 | v38.57,66.67 38.57,65.4 | 38.57,65.4 R25.1
  Bottom 0.254: v34.76,66.16 35.27,66.67 v38.57,66.67
N$15
  Top 0.254: 18.25,74.29 20.79,74.29 L1.1 23.33,74.29 23.33,73.02 IC2.1 | 10.63,74.29 9.36,73.02 9.36,70.48 6.82,67.94 C18.1 | 10.63,74.29 11.9,73.02 11.9,67.94 14.44,65.4 C25.1 | 18.25,74.29 15.71,74.29 15.71,75.56 10.63,75.56 10.63,74.29 | 18.25,74.29 C21.1 | 10.63,74.29 R26.1
N$16
  Top 0.254: C19.1 3.01,67.94 1.74,66.67 1.74,62.86 3.01,61.59 R21.2
N$17
  Top 0.254: 6.82,65.4 3.01,65.4 C19.2 | R22.2 6.82,65.4 | 6.82,65.4 C18.2
N$18
  Top 0.254: IC2.3 27.14,70.48 27.14,71.75 IC2.2 23.33,71.75 L1.2 20.79,71.75 18.25,71.75 | 14.44,67.94 14.44,71.75 | 18.25,67.94 20.79,67.94 L2.1 | 14.44,67.94 18.25,67.94 | C25.2 14.44,67.94 | 18.25,67.94 C22.1 | 14.44,71.75 18.25,71.75 | 18.25,71.75 C21.2 | 14.44,71.75 C26.1
N$19  (via drill 0.61)
  Top 0.254: v13.02,69.08 13.02,72.82 14.44,74.29 C26.2 | R12.1 10.63,65.4 v11.9,64.13 15.71,64.13 16.98,65.4 18.25,65.4 | 18.25,65.4 20.79,65.4 L2.2 23.33,65.4 24.6,66.67 24.6,69.21 IC2.4 28.41,69.21 28.41,75.56 C27.1 | 18.25,65.4 C22.2
  Bottom 0.254: v13.02,69.08 13.04,64.13 v11.9,64.13
N$20
  Top 0.254: 38.57,62.86 41.11,62.86 C24.2 | 32.22,62.86 32.22,65.4 IC2.8 | 32.22,62.86 38.57,62.86 | 38.57,62.86 R25.2 | D9.C 32.22,62.86
N$21  (via drill 0.61)
  Top 0.254: C20.2 18.25,61.59 19.52,62.86 23.33,62.86 23.33,61.59 23.08,61.59 | 23.08,61.59 R23.1 | 23.08,61.59 25.87,61.59 27.14,62.86 D9.A 28.33,62.86 v30.87,65.4 30.9,65.42 | 30.95,67.94 30.9,67.94 | 30.95,67.94 30.95,69.21 IC2.11 | v30.87,67.94 30.95,67.94
  Bottom 0.254: 30.9,67.96 30.9,67.94 v30.87,67.94 30.95,67.94 30.95,65.4 v30.87,65.4 30.9,65.4
N$22
  Top 0.254: 18.5,47.62 18.42,47.53 C53.1 18.25,47.62 19.01,46.86 23.58,46.86 25.23,45.21 IC3.4
N$23
  Top 0.254: IC3.5 26.5,44.95 23.84,47.62 20.79,47.62 19.27,49.14 18.25,49.14 C53.2
N$24  (via drill 0.61)
  Top 0.254: IC3.2 22.7,44.7 v22.82,44.83 | 18.25,51.68 C54.1 18.25,51.91 18.27,51.94 19.75,50.47 v19.75,50.44
  Bottom 0.254: 22.31,44.83 v22.82,44.83 19.77,47.87 19.72,47.87 19.72,50.44 v19.75,50.44
N$25
  Top 0.254: IC3.6 27.72,42.72 27.65,42.79 27.9,43.05 27.9,44.57 32.73,44.57 33.24,44.06 C55.2 33.49,44.06 32.98,44.57
N$26  (via drill 0.61)
  Top 0.254: v29.68,48.89 27.65,48.89 25.11,51.43 25.11,52.45 25.18,52.52 IC3.13 | v8.34,52.7 8.34,40 J1.12 6.82,38.73
  Bottom 0.254: v8.34,52.7 27.14,52.7 29.68,50.16 v29.68,48.89
N$27
  Top 0.254: 83.6,36.19 83.6,34.16 89.45,34.16 92.49,37.46 IC4.15 92.49,38.73 | 83.6,36.19 C11.1 | Y1.1 83.6,36.19
N$28
  Top 0.254: 91.22,38.73 IC4.16 91.22,37.46 89.95,36.19 87.41,36.19 Y1.4 86.14,36.19 C10.1
N$29
  Top 0.254: LED3.K 74.97,24.76 R5.1
N$30
  Top 0.254: LED4.K 77.51,59.05 81.32,59.05 R6.1
N$31  (via drill 0.61)
  Top 0.254: D12.A D11.C | R7.2 68.62,38.73 64.81,34.92 C38.2
  Top 0.813: D11.C 67.43,28.48 v67.35,28.57
  Bottom 0.813: C38.2 65.06,34.92 67.35,32.63 v67.35,28.57
N$32  (via drill 0.61)
  Top 0.254: C37.2 63.54,48.89 | 81.32,18.41 81.32,22.22 R10.1 | 80.05,12.06 81.32,12.06 | 81.32,12.06 D3.C | 80.05,12.06 R11.1 | 81.32,12.06 81.32,18.41 | 81.32,18.41 Q2.3 | v78.78,10.79 80.05,12.06 | v52.9,31.44 52.77,31.44 52.77,50.11 53.35,50.69 v53.35,50.74
  Bottom 0.254: v53.35,50.74 55.38,50.74 57.19,48.89 C37.2 | v78.78,10.79 63.54,10.79 63.54,19.68 57.19,26.03 52.9,26.03 v52.9,31.44
N$33
  Top 0.254: D3.A 87.67,12.06 87.67,14.6 D2.A
N$34
  Top 0.254: 81.32,75.56 87.67,75.56 87.67,71.75 R27.1 90.21,71.75 91.48,71.75 C29.1 | 81.32,75.56 81.32,74.29 80.05,73.02 80.05,67.94 IC5.5 | 81.32,75.56 C33.2
N$35  (via drill 0.61)
  Top 0.254: 88.94,65.4 91.48,65.4 | 91.48,69.21 90.21,69.21 R27.2 | 91.48,65.4 91.48,69.21 | 91.48,65.4 C30.1 | 91.48,69.21 C29.2 | IC5.6 IC5.9 84.62,66.67 v85.13,66.16 | v88.94,66.67 88.94,65.4 | 88.94,65.4 R28.1
  Bottom 0.254: v85.13,66.16 85.64,66.67 v88.94,66.67
N$36
  Top 0.254: C13.1 53.38,67.94 52.11,66.67 52.11,62.86 53.38,61.59 R1.2
N$37
  Top 0.254: 57.19,65.4 53.38,65.4 C13.2 | R15.2 57.19,65.4 | 57.19,65.4 C12.2
N$38
  Top 0.254: 68.62,74.29 71.16,74.29 L3.1 73.7,74.29 73.7,73.02 IC5.1 | 61,74.29 59.73,73.02 59.73,70.48 57.19,67.94 C12.1 | 61,74.29 62.27,73.02 62.27,67.94 64.81,65.4 C31.1 | 68.62,74.29 66.08,74.29 66.08,75.56 61,75.56 61,74.29 | 68.62,74.29 C17.1 | 61,74.29 R29.1
N$39
  Top 0.254: IC5.3 77.51,70.48 77.51,71.75 IC5.2 73.7,71.75 L3.2 71.16,71.75 68.62,71.75 | 64.81,67.94 64.81,71.75 | 68.62,67.94 71.16,67.94 L4.1 | 64.81,67.94 68.62,67.94 | C31.2 64.81,67.94 | 68.62,67.94 C28.1 | 64.81,71.75 68.62,71.75 | 68.62,71.75 C17.2 | 64.81,71.75 C32.1
N$40  (via drill 0.61)
  Top 0.254: v63.39,69.08 63.39,72.82 64.81,74.29 C32.2 | R8.1 61,65.4 v62.27,64.13 66.08,64.13 67.35,65.4 68.62,65.4 | 68.62,65.4 71.16,65.4 L4.2 73.7,65.4 74.97,66.67 74.97,69.21 IC5.4 78.78,69.21 78.78,75.56 C33.1 | 68.62,65.4 C28.2
  Bottom 0.254: v63.39,69.08 63.41,64.13 v62.27,64.13
N$41
  Top 0.254: 88.94,62.86 91.48,62.86 C30.2 | 82.59,62.86 82.59,65.4 IC5.8 | 82.59,62.86 88.94,62.86 | 88.94,62.86 R28.2 | D10.C 82.59,62.86
N$42  (via drill 0.61)
  Top 0.254: C15.2 68.62,61.59 69.89,62.86 73.7,62.86 73.7,61.59 73.44,61.59 | 73.44,61.59 R16.1 | 73.44,61.59 76.24,61.59 77.51,62.86 D10.A 78.7,62.86 v81.24,65.4 81.27,65.42 | 81.32,67.94 81.27,67.94 | 81.32,67.94 81.32,69.21 IC5.11 | v81.24,67.94 81.32,67.94
  Bottom 0.254: 81.27,67.96 81.27,67.94 v81.24,67.94 81.32,67.94 81.32,65.4 v81.24,65.4 81.27,65.4
N$43
  Top 0.254: DPP1.A 90.21,22.22 92.75,24.76 RPP1.2
N$44
  Top 0.254: Q2.1 83.86,17.14 86.4,17.14 R13.2
N$45
  Top 0.254: C40.1 68.62,43.3 69.2,42.72 IC6.1
N$46
  Top 0.254: IC6.3 74.33,45.46 73.7,46.1 72.68,46.1 71.67,45.08 68.87,45.08 68.78,45.17 C40.2
N$47
  Top 0.254: 68.87,47.62 68.78,47.53 C41.1 68.62,47.62 69.38,46.86 73.95,46.86 75.6,45.21 IC6.4
N$48
  Top 0.254: IC6.5 76.87,44.95 74.21,47.62 71.16,47.62 69.63,49.14 68.62,49.14 C41.2
N$49  (via drill 0.61)
  Top 0.254: v85.38,47.62 77.76,47.62 74.46,50.92 74.46,52.45 74.38,52.52 IC6.14 | v76.24,40 74.97,38.73 v72.43,38.73
  Bottom 0.254: v76.24,40 77.51,40 85.13,47.62 v85.38,47.62 | v72.43,38.73 69.89,41.27 57.19,41.27 J4.13
N$50  (via drill 0.61)
  Top 0.254: v80.05,48.89 78.02,48.89 75.48,51.43 75.48,52.45 75.55,52.52 IC6.13 | v58.71,52.7 58.71,40 J4.12 57.19,38.73
  Bottom 0.254: v58.71,52.7 77.51,52.7 80.05,50.16 v80.05,48.89
N$51  (via drill 0.61)
  Top 0.254: IC6.2 73.06,44.7 v73.19,44.83 | 68.62,51.68 C42.1 68.62,51.91 68.64,51.94 70.12,50.47 v70.12,50.44
  Bottom 0.254: 72.68,44.83 v73.19,44.83 70.14,47.87 70.09,47.87 70.09,50.44 v70.12,50.44
N$52
  Top 0.254: IC6.6 78.09,42.72 78.02,42.79 78.27,43.05 78.27,44.57 83.1,44.57 83.6,44.06 C43.2 83.86,44.06 83.35,44.57
NEUT  (via drill 0.61)
  Top 0.254: PTC.2 5.55,10.79 | 4.28,32.38 J1.2 | VDR.P$2 9.36,17.14
  Top 0.813: 4.28,32.38 5.55,31.11 5.55,27.3 9.36,23.49 9.36,17.14 | 5.55,10.79 v7.33,10.79 | v6.57,15.87 VDR.P$2
  Bottom 0.813: v6.57,15.87 6.57,11.55 v7.33,10.79
NEUT1  (via drill 0.61)
  Top 0.254: PTC1.2 55.92,10.79 | 54.65,32.38 J4.2 | VDR1.P$2 59.73,17.14
  Top 0.813: 54.65,32.38 55.92,31.11 55.92,27.3 59.73,23.49 59.73,17.14 | 55.92,10.79 v57.7,10.79 | v56.93,15.87 VDR1.P$2
  Bottom 0.813: v56.93,15.87 56.93,11.55 v57.7,10.79
RB1  (via drill 0.61)
  Top 0.254: 96.3,38.73 IC4.12 96.56,38.73 96.53,37.84 97.8,36.57 v97.83,32.89 | v92.24,18.92 92.24,15.11 J3.8
  Bottom 0.254: v97.83,32.89 98.59,31.87 98.59,30.6 92.24,23.49 v92.24,18.92
RB2  (via drill 0.61)
  Top 0.254: 95.03,38.73 IC4.13 95.29,38.73 v95.29,33.65
  Bottom 0.254: 84.31,19.63 83.1,18.41 76.24,18.41 76.24,20.95 77.56,22.27 77.61,22.22 81.42,22.22 87.92,28.72 87.95,28.7 90.13,28.7 95.08,33.65 v95.29,33.65 | 84.31,19.63 84.37,19.68 | J3.6 91.3,15.62 87.24,19.68 84.31,19.68 84.29,19.65 84.31,19.63
RB6  (via drill 0.61)
  Top 0.254: 45.94,38.73 IC1.12 46.19,38.73 46.16,37.84 47.44,36.57 v47.46,32.89 | v41.87,18.92 41.87,15.11 J2.8
  Bottom 0.254: v47.46,32.89 48.22,31.87 48.22,30.6 41.87,23.49 v41.87,18.92
RB7  (via drill 0.61)
  Top 0.254: 44.67,38.73 IC1.13 44.92,38.73 v44.92,33.65
  Bottom 0.254: 33.95,19.63 32.73,18.41 25.87,18.41 25.87,20.95 27.19,22.27 27.24,22.22 31.05,22.22 37.55,28.72 37.58,28.7 39.76,28.7 44.72,33.65 v44.92,33.65 | 33.95,19.63 34,19.68 | J2.6 40.93,15.62 36.87,19.68 33.95,19.68 33.92,19.65 33.95,19.63
SIN  (via drill 0.61)
  Top 0.254: IC1.8 47.21,27.55 v47.71,27.05 | IC3.12 26.5,51.3 27.9,49.91 v43.9,49.91
  Bottom 0.254: v47.71,27.05 48.98,28.32 48.98,49.91 v43.9,49.91
SIN1  (via drill 0.61)
  Top 0.254: IC4.8 97.57,27.55 v98.08,27.05 | IC6.12 76.87,51.3 78.27,49.91 v94.27,49.91
  Bottom 0.254: v98.08,27.05 99.35,28.32 99.35,49.91 v94.27,49.91
SOUT
  Top 0.254: IC3.11 27.77,51.3 28.16,50.92 45.17,50.92 47.46,48.66 47.46,38.73 IC1.11
SOUT1
  Top 0.254: IC6.11 78.14,51.3 78.52,50.92 95.54,50.92 97.83,48.66 97.83,38.73 IC4.11
SWIN  (via drill 0.61)
  Top 0.254: 40.86,28.57 IC1.3 41.11,28.57 41.11,29.84 37.81,33.14 30.44,33.14 30.44,35.68 29.93,36.19 29.68,36.19 | 27.14,36.19 27.14,33.65 | 27.14,33.65 27.14,29.84 C4.1 | 27.14,33.65 R4.1 | v25.87,37.46 27.14,36.19 | S1.BP 29.27,40.61 29.17,40.51 29.27,40.41 S1.B 29.68,36.19 | 27.14,36.19 29.68,36.19
  Bottom 0.254: v25.87,37.46 19.52,43.81 6.82,43.81 J1.14
SWIN1  (via drill 0.61)
  Top 0.254: 91.22,28.57 IC4.3 91.48,28.57 91.48,29.84 88.18,33.14 80.81,33.14 80.81,35.68 80.3,36.19 80.05,36.19 | 77.51,36.19 77.51,33.65 | 77.51,33.65 77.51,29.84 C35.1 | 77.51,33.65 R30.1 | v76.24,37.46 77.51,36.19 | S2.BP 79.64,40.61 79.54,40.51 79.64,40.41 S2.B 80.05,36.19 | 77.51,36.19 80.05,36.19
  Bottom 0.254: v76.24,37.46 69.89,43.81 57.19,43.81 J4.14
UTIL  (via drill 0.61)
  Top 0.254: 45.94,28.57 IC1.7 46.19,28.57 v46.19,36.19 | v7,50.44 5.55,48.89 5.55,38.73 4.28,37.46 J1.4
  Bottom 0.254: v7,50.44 15.71,50.41 15.71,48.89 20.79,43.81 27.14,43.81 32.22,48.89 38.06,48.89 46.19,40.76 v46.19,36.19
UTIL1  (via drill 0.61)
  Top 0.254: 96.3,28.57 IC4.7 96.56,28.57 v96.56,36.19 | v57.37,50.44 55.92,48.89 55.92,38.73 54.65,37.46 J4.4
  Bottom 0.254: v57.37,50.44 66.08,50.41 66.08,48.89 71.16,43.81 77.51,43.81 82.59,48.89 88.43,48.89 96.56,40.76 v96.56,36.19
VPP
  Top 0.254: 44.92,24.76 44.92,26.03 42.38,26.03 42.38,28.57 IC1.4 | 42.38,20.95 44.92,23.49 44.92,24.76 | 42.38,20.95 39.84,18.41 DPP.C | 44.92,24.76 C3.1 | 42.38,20.95 43.65,20.95 J2.2
VPP1
  Top 0.254: 95.29,24.76 95.29,26.03 92.75,26.03 92.75,28.57 IC4.4 | 92.75,20.95 95.29,23.49 95.29,24.76 | 92.75,20.95 90.21,18.41 DPP1.C | 95.29,24.76 C9.1 | 92.75,20.95 94.02,20.95 J3.2
XIN  (via drill 0.61)
  Top 0.254: v41.11,52.45 41.11,52.7 43.65,52.7 | 43.65,52.7 43.9,52.7 | 48.48,38.73 48.73,38.48 48.69,38.44 IC1.10 48.73,38.73 48.73,48.89 44.92,52.7 43.65,52.7 | IC2.10 34.76,67.94 v34.76,67.69
  Bottom 0.254: v41.11,52.45 41.11,67.69 v34.76,67.69
XIN1  (via drill 0.61)
  Top 0.254: v91.48,52.45 91.48,52.7 94.02,52.7 | 94.02,52.7 94.27,52.7 | 98.84,38.73 99.1,38.48 99.06,38.44 IC4.10 99.1,38.73 99.1,48.89 95.29,52.7 94.02,52.7 | IC5.10 85.13,67.94 v85.13,67.69
  Bottom 0.254: v91.48,52.45 91.48,67.69 v85.13,67.69
XOUT  (via drill 0.61)
  Top 0.254: 48.48,28.57 IC1.9 48.73,28.57 48.73,29.84 v47.21,31.36 | v36,24.05 35.95,24.05 35.9,24 36.03,23.87 R20.1
  Bottom 0.254: v47.21,31.36 41.11,24.76 36.72,24.76 v36,24.05 35.95,24
XOUT1  (via drill 0.61)
  Top 0.254: 98.84,28.57 IC4.9 99.1,28.57 99.1,29.84 v97.57,31.36 | v86.37,24.05 86.32,24.05 86.27,24 86.4,23.87 R13.1
  Bottom 0.254: v97.57,31.36 91.48,24.76 87.08,24.76 v86.37,24.05 86.32,24
ZEROX  (via drill 0.61)
  Top 0.254: v44.92,31.11 44.92,28.57 IC1.6 | v38.57,26.03 38.57,25.95 37.3,24.68 37.3,17.14 39.84,14.6 R17.2
  Bottom 0.254: v44.92,31.11 39.84,26.03 v38.57,26.03
ZEROX1  (via drill 0.61)
  Top 0.254: v95.29,31.11 95.29,28.57 IC4.6 | v88.94,26.03 88.94,25.95 87.67,24.68 87.67,17.14 90.21,14.6 R9.2
  Bottom 0.254: v95.29,31.11 90.21,26.03 v88.94,26.03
